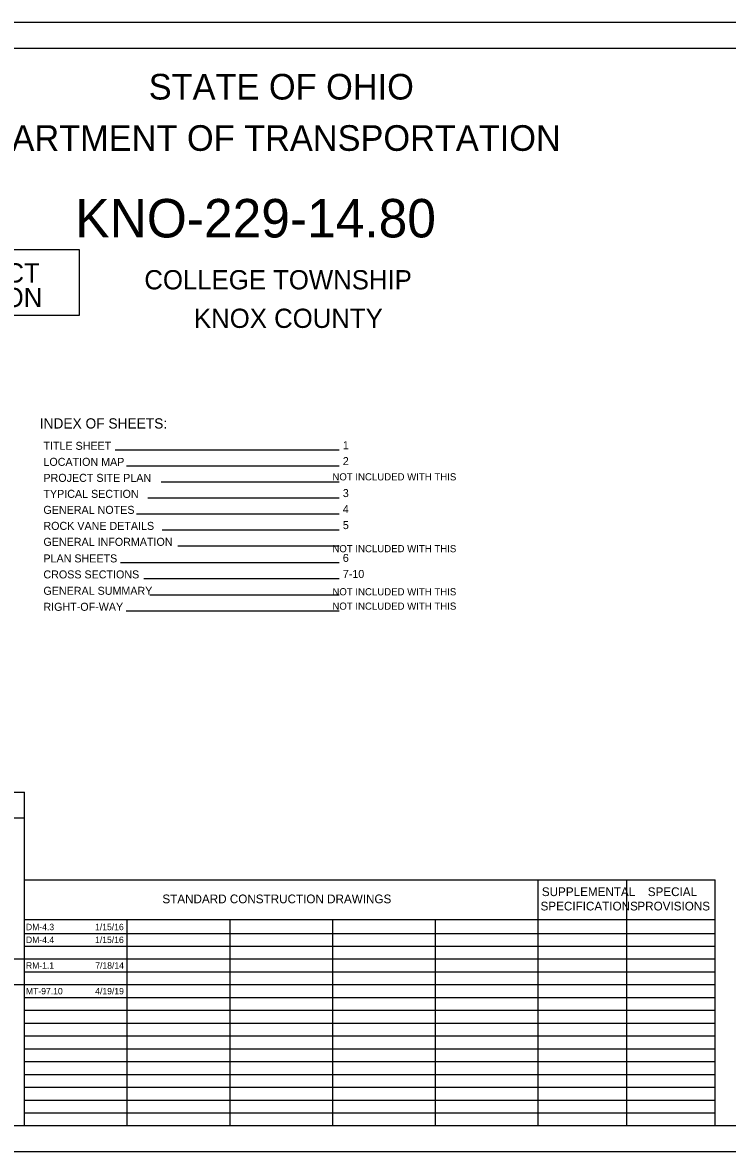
# Model space of a CAD drawing. Extents: x 41.3 to 81.6, y -19.3 to 2.7.
# Drawn here: x 52.78 to 66.5, y -19.27 to 2.73 of the extents above; entities that cross this region are included whole.
import ezdxf

# ---------------------------------------------------------------- set-up
doc = ezdxf.new("R2010")
doc.units = 0
for name, color, linetype in [('Default', 7, 'Continuous'), ('SH_Border', 7, 'Continuous'), ('SH_Cut_Line', 7, 'Continuous'), ('SH_Data', 7, 'Continuous')]:
    doc.layers.add(name, color=color, linetype=linetype)

msp = doc.modelspace()

# ---------------------------------------------------------------- linework, layer by layer
at = {"layer": 'Default'}
for p, q in [((54.578, -5.593), (58.939, -5.593)), ((54.801, -5.906), (58.939, -5.906)), ((55.475, -6.218), (58.939, -6.218)), ((55.213, -6.53), (58.939, -6.53)), ((54.994, -6.842), (58.939, -6.842)), ((55.492, -7.154), (58.939, -7.154)), ((55.797, -7.465), (58.939, -7.465)), ((54.685, -7.787), (58.939, -7.787)), ((55.134, -8.099), (58.939, -8.099)), ((55.253, -8.418), (58.939, -8.418)), ((54.793, -8.73), (58.939, -8.73))]:
    msp.add_line(p, q, dxfattribs=at)
msp.add_lwpolyline([(50.517, -1.686), (53.875, -1.686), (53.875, -2.978), (50.517, -2.978)], close=True, dxfattribs=at)
at = {"layer": 'SH_Border'}
msp.add_lwpolyline([(42.765, 2.234), (74.765, 2.234), (74.765, -18.766), (42.765, -18.766)], close=True, dxfattribs=at)
at = {"layer": 'SH_Cut_Line'}
msp.add_lwpolyline([(41.265, -19.266), (75.265, -19.266), (75.265, 2.734), (41.265, 2.734)], close=True, dxfattribs=at)
at = {"layer": 'SH_Data'}
for p, q in [((50.015, -12.266), (52.815, -12.266)), ((52.815, -18.766), (52.815, -12.266)), ((50.015, -12.766), (52.815, -12.766)), ((52.815, -13.974), (66.265, -13.974)), ((62.815, -18.766), (62.815, -13.974)), ((64.54, -18.766), (64.54, -13.974)), ((66.265, -18.766), (66.265, -13.974)), ((52.815, -14.745), (66.265, -14.745)), ((54.815, -18.766), (54.815, -14.745)), ((56.815, -18.766), (56.815, -14.745)), ((58.815, -18.766), (58.815, -14.745)), ((60.815, -18.766), (60.815, -14.745)), ((52.815, -15.016), (66.265, -15.016)), ((52.815, -15.266), (66.265, -15.266)), ((50.015, -15.516), (52.815, -15.516)), ((52.815, -15.516), (66.265, -15.516)), ((52.815, -15.766), (66.265, -15.766)), ((50.015, -16.016), (52.815, -16.016)), ((52.815, -16.016), (66.265, -16.016)), ((52.815, -16.266), (66.265, -16.266)), ((52.815, -16.516), (66.265, -16.516)), ((52.815, -16.766), (66.265, -16.766)), ((52.815, -17.016), (66.265, -17.016)), ((52.815, -17.266), (66.265, -17.266)), ((52.815, -17.516), (66.265, -17.516)), ((52.815, -17.766), (66.265, -17.766)), ((52.815, -18.016), (66.265, -18.016)), ((52.815, -18.266), (66.265, -18.266)), ((52.815, -18.516), (66.265, -18.516))]:
    msp.add_line(p, q, dxfattribs=at)

# ---------------------------------------------------------------- texts
at = {"layer": 'Default'}
for s, height, p in [('STATE OF OHIO', 0.5, (55.232, 1.234)), ('DEPARTMENT OF TRANSPORTATION', 0.5, (51.184, 0.234)), ('KNO-229-14.80', 0.75, (53.801, -1.454)), ('PROJECT ', 0.375, (50.768, -2.332)), ('COLLEGE TOWNSHIP', 0.375, (55.146, -2.466)), ('LOCATION ', 0.375, (50.595, -2.811)), ('KNOX COUNTY', 0.375, (56.113, -3.217)), ('TITLE SHEET                       ', 0.15597, (53.181, -5.593)), ('1', 0.156, (59.012, -5.581)), ('LOCATION MAP', 0.15597, (53.181, -5.905)), ('2', 0.156, (59.012, -5.89)), ('PROJECT SITE PLAN', 0.15597, (53.181, -6.217)), ('TYPICAL SECTION', 0.15597, (53.181, -6.529)), ('3', 0.156, (59.012, -6.514)), ('GENERAL NOTES', 0.15597, (53.181, -6.841)), ('4', 0.156, (59.012, -6.826)), ('ROCK VANE DETAILS', 0.15597, (53.181, -7.153)), ('5', 0.156, (59.012, -7.138)), ('GENERAL INFORMATION       ', 0.15597, (53.181, -7.464)), ('PLAN SHEETS', 0.15597, (53.181, -7.787)), ('6', 0.156, (59.012, -7.778)), ('CROSS SECTIONS', 0.15597, (53.181, -8.099)), ('7-10', 0.156, (59.012, -8.09)), ('GENERAL SUMMARY  ', 0.15597, (53.181, -8.418)), ('RIGHT-OF-WAY', 0.15597, (53.181, -8.73)), ('DM-4.3', 0.125, (52.841, -14.955)), ('1/15/16', 0.125, (54.187, -14.955)), ('DM-4.4', 0.125, (52.841, -15.205)), ('1/15/16', 0.125, (54.187, -15.205)), ('RM-1.1', 0.125, (52.841, -15.705)), ('7/18/14', 0.125, (54.191, -15.705)), ('MT-97.10', 0.125, (52.841, -16.205)), ('4/19/19', 0.125, (54.19, -16.205))]:
    msp.add_text(s, height=height, dxfattribs=at).set_placement(p)
at = {"layer": 'SH_Data'}
for s, height, p in [('INDEX OF SHEETS:', 0.2, (53.109, -5.178)), ('NOT INCLUDED WITH THIS ', 0.14, (58.809, -6.189)), ('NOT INCLUDED WITH THIS ', 0.14, (58.809, -7.589)), ('NOT INCLUDED WITH THIS  ', 0.14, (58.809, -8.429)), ('NOT INCLUDED WITH THIS  ', 0.14, (58.809, -8.709)), ('STANDARD CONSTRUCTION DRAWINGS', 0.17, (55.498, -14.43)), ('SUPPLEMENTAL', 0.17, (62.888, -14.29)), ('SPECIAL', 0.17, (64.951, -14.29)), ('SPECIFICATIONS', 0.17, (62.863, -14.57)), ('PROVISIONS', 0.17, (64.749, -14.57))]:
    msp.add_text(s, height=height, dxfattribs=at).set_placement(p)

doc.saveas('drawing.dxf')
